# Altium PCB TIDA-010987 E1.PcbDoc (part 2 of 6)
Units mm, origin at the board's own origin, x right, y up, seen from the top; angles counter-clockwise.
Board outline 154.15 x 103.76 mm, 4 copper layers (5V, GND, MidSupply, -5V), stack 1.787 mm thick; 92 components, 52 nets, 1640 pads, 56 vias.
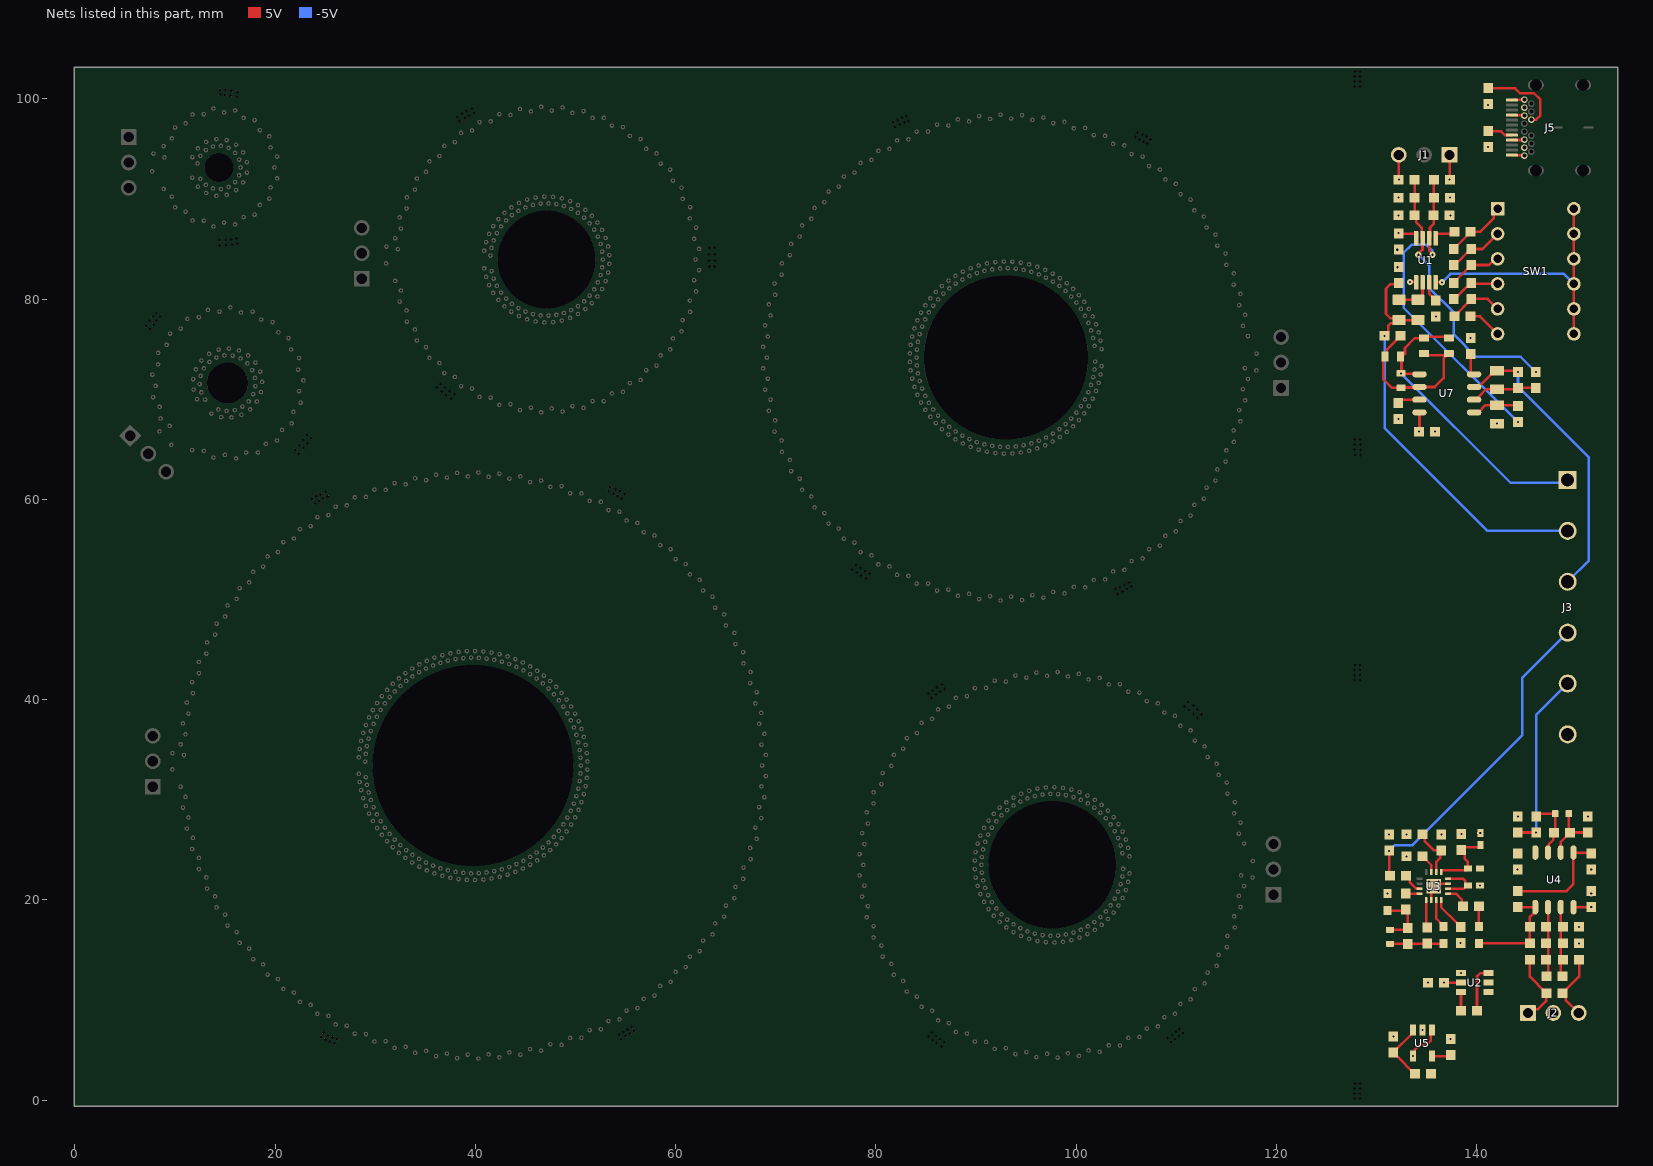
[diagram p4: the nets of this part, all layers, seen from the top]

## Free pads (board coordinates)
  round 0.254 hole 0.3 unplated mask+0: 0(7.105,77.291) 0(7.447,77.804) 0(7.521,77.001) 0(7.808,78.235) 0(7.843,77.464) 0(8.183,77.854) 0(8.189,78.604) 0(8.511,78.249) 0(14.482,100.405) 0(14.501,100.898) 0(15.028,100.383) 0(15.074,100.88) 0(15.577,100.316) 0(15.675,100.803) 0(16.132,100.178) 0(16.254,100.696) 0(21.983,64.939) 0(22.335,64.594) 0(22.448,65.44) 0(22.826,65.119) 0(22.847,65.936) 0(23.196,66.431) 0(23.24,65.629) 0(23.597,66.14) 0(23.717,60.012) 0(23.982,59.564) 0(24.16,60.277) 0(24.398,59.844) 0(24.566,60.496) 0(24.594,6.316) 0(24.805,60.077) 0(24.821,6.744) 0(25.026,6.067) 0(25.029,60.705) 0(25.257,60.291) 0(25.316,6.461) 0(25.498,5.843) 0(25.74,6.271) 0(25.945,5.627) 0(26.198,6.085) 0(53.282,60.84) 0(53.479,61.234) 0(53.801,60.602) 0(54.003,61.04) 0(54.207,60.344) 0(54.35,6.556) 0(54.455,60.817) 0(54.546,6.125) 0(54.659,60.091) 0(54.794,6.805) 0(54.91,60.532) 0(55.027,6.378) 0(55.21,7.056) 0(55.461,6.632) 0(55.618,7.275) 0(55.869,6.883)
  oval 0.2x0.254 hole 0.3 unplated mask+0: 0(14.462,85.357) 0(14.465,85.873) 0(15.041,85.873) 0(15.083,85.393) 0(15.615,85.945) 0(15.687,85.465) 0(16.134,86.05) 0(16.26,85.567)
  round 0.2 hole 0.3 unplated mask+0: 0(36.175,71.169) 0(36.513,71.523) 0(36.651,70.754) 0(36.961,71.144) 0(37.081,70.435) 0(37.402,70.823) 0(37.579,70.078) 0(37.917,70.524) 0(38.178,98.185) 0(38.439,97.801) 0(38.697,98.512) 0(38.951,98.073) 0(39.136,98.767) 0(39.363,98.317) 0(39.68,99.031) 0(39.889,98.582) 0(63.354,83.866) 0(63.361,84.44) 0(63.374,83.257) 0(63.397,85.094) 0(63.895,85.143) 0(63.908,83.238) 0(63.957,83.856) 0(63.957,84.427) 0(77.646,52.982) 0(78.018,53.44) 0(78.112,52.671) 0(78.467,53.122) 0(78.546,52.385) 0(78.906,52.841) 0(79.042,52.113) 0(79.348,52.602) 0(81.694,97.658) 0(81.927,97.201) 0(82.165,97.899) 0(82.392,97.415) 0(82.636,98.11) 0(82.852,97.613) 0(83.064,98.285) 0(83.277,97.759) 0(85.251,6.337) 0(85.253,40.596) 0(85.551,40.175) 0(85.634,6.749) 0(85.648,5.993) 0(85.678,40.922) 0(85.996,40.488) 0(86.008,6.417) 0(86.079,5.69) 0(86.136,41.23) 0(86.416,6.122) 0(86.429,40.788) 0(86.543,5.376) 0(86.592,41.51) 0(86.824,5.812) 0(86.85,41.057) 0(103.923,51.035) 0(104.142,50.566) 0(104.404,51.241) 0(104.646,50.802) 0(104.84,51.456) 0(105.085,51.032) 0(105.278,51.699) 0(105.535,51.299) 0(105.915,96.191) 0(106.159,96.628) 0(106.333,95.955) 0(106.621,96.435) 0(106.718,95.754) 0(107.033,96.212) 0(107.097,95.518) 0(107.455,95.949) 0(109.156,6.208) 0(109.458,5.803) 0(109.598,6.505) 0(109.904,6.116) 0(109.958,6.825) 0(110.291,6.395) 0(110.331,7.093) 0(110.703,6.677) 0(110.843,39.299) 0(111.193,39.762) 0(111.266,38.943) 0(111.704,38.562) 0(111.715,39.398) 0(112.113,38.136) 0(112.124,39.005) 0(112.536,38.511) 0(127.823,0.148) 0(127.823,0.648) 0(127.823,1.166) 0(127.823,41.952) 0(127.823,42.452) 0(127.823,42.969) 0(127.823,101.218) 0(127.823,101.718) 0(127.823,102.235) 0(127.827,64.953) 0(127.831,65.951) 0(127.834,64.447) 0(127.834,65.474) 0(127.845,1.636) 0(127.845,43.439) 0(127.845,102.705) 0(128.362,0.148) 0(128.362,0.647) 0(128.362,1.166) 0(128.362,1.636) 0(128.362,41.952) 0(128.362,42.451) 0(128.362,42.969) 0(128.362,43.439) 0(128.362,101.218) 0(128.362,101.716) 0(128.362,102.235) 0(128.362,102.705) 0(128.381,65.977) 0(128.387,65.452) 0(128.393,64.435) 0(128.393,64.934)
  round 0.45 hole 0.2 mask+0: 3(7.724,92.755) 3(9.646,65.446) 3(31.087,83.562) 3(117.66,23.878) 3(118.028,74.537) 4(7.858,94.525) 4(8.461,66.786) 4(31.133,85.225) 4(117.623,22.229) 4(117.999,72.885) 12(12.259,93.539) 12(13.022,69.953) 12(41.515,84.339) 12(101.914,73.758) 12(104.705,23.102) 13(8.962,94.156) 13(9.484,67.342) 13(32.273,84.985) 13(116.48,22.453) 13(116.853,73.096) 14(11.747,94.166) 14(12.211,69.994) 14(40.896,84.821) 14(102.552,73.305) 14(105.335,22.64) 15(8.573,68.071) 15(8.883,95.276) 15(32.001,86.071) 15(116.776,21.373) 15(117.166,72.008) 16(12.548,94.285) 16(12.634,70.686) 16(41.624,85.115) 16(101.844,72.971) 16(104.619,22.326) 17(8.484,69.234) 17(9.696,96.051) 17(32.562,87.041) 17(116.251,20.385) 17(116.666,70.992) 18(11.872,70.964) 18(12.297,95.055) 18(41.078,85.679) 18(102.44,72.463) 18(105.195,21.797) 19(7.828,70.199) 19(10.027,97.124) 19(32.443,88.155) 19(116.427,19.28) 19(116.882,69.88) 20(12.48,71.501) 20(13.087,94.876) 20(41.84,85.868) 20(101.705,72.194) 20(104.448,21.564) 21(8.086,71.337) 21(11.066,97.553) 21(33.134,89.036) 21(115.796,18.355) 21(116.294,68.912) 22(11.833,71.992) 22(13.131,95.684) 22(41.378,86.502) 22(102.254,71.635) 22(104.962,20.975) 23(7.744,72.453) 23(11.762,98.434) 23(33.172,90.156) 23(115.849,17.237) 23(116.411,67.786) 24(12.573,72.326) 24(13.803,95.232) 24(42.159,86.583) 24(101.498,71.432) 24(104.194,20.826) 25(8.326,73.464) 25(12.885,98.458) 25(33.979,90.933) 25(115.12,16.388) 25(115.74,66.874) 26(12.099,72.985) 26(14.136,95.97) 26(41.789,87.276) 26(101.995,70.827) 26(104.641,20.183) 27(8.327,74.631) 27(13.852,99.029) 27(34.172,92.036) 27(115.051,15.271) 27(115.757,65.741) 28(12.905,73.086) 28(14.599,95.306) 28(42.574,87.248) 28(101.224,70.691) 28(103.861,20.12) 29(9.182,75.426) 29(14.908,98.646) 29(35.079,92.693) 29(114.233,14.507) 29(115.008,64.892) 30(12.646,73.856) 30(15.176,95.874) 30(42.304,87.985) 30(101.666,70.045) 30(104.234,19.432) 31(9.527,76.54) 31(16.017,98.829) 31(35.423,93.759) 31(114.04,13.404) 31(114.924,63.763) 32(13.446,73.715) 32(15.368,95.087) 32(43.077,87.848) 32(100.886,69.977) 32(103.452,19.454) 33(10.578,77.048) 33(16.863,98.09) 33(36.413,94.284) 33(113.143,12.735) 33(114.103,62.983) 34(13.426,74.527) 34(16.111,95.408) 34(42.913,88.616) 34(101.269,69.295) 34(103.747,18.73) 35(11.236,78.011) 35(17.963,97.86) 35(36.903,95.291) 35(112.831,11.66) 35(113.92,61.865) 36(14.148,74.156) 36(16.006,94.606) 36(43.66,88.372) 36(100.486,69.296) 36(102.973,18.838) 37(12.39,78.186) 37(18.485,96.865) 37(37.956,95.673) 37(111.866,11.093) 37(113.033,61.161) 38(14.368,74.938) 38(16.815,94.636) 38(43.604,89.155) 38(100.807,68.583) 38(103.186,18.086) 39(13.303,78.913) 39(19.427,96.253) 39(38.581,96.602) 39(111.437,10.059) 39(112.753,60.064) 40(14.95,74.371) 40(16.427,93.926) 40(44.309,88.81) 40(100.028,68.653) 40(102.428,18.278) 41(14.457,78.74) 41(19.555,95.137) 41(39.677,96.833) 41(110.415,9.602) 41(111.807,59.441) 42(15.39,75.053) 42(17.193,93.662) 42(44.363,89.594) 42(100.284,67.914) 42(102.558,17.507) 43(15.544,79.165) 43(20.212,94.226) 43(40.425,97.667) 43(109.875,8.622) 43(111.43,58.373) 44(15.779,74.34) 44(16.574,93.14) 44(45.013,89.154) 44(99.514,68.053) 44(101.826,17.782) 45(16.596,78.66) 45(19.928,93.14) 45(41.543,97.743) 45(108.81,8.28) 45(110.433,57.836) 46(16.401,74.862) 46(17.193,92.617) 46(45.176,89.922) 46(99.704,67.294) 46(101.869,17.001) 47(17.76,78.746) 47(20.212,92.053) 47(42.4,98.465) 47(108.165,7.365) 47(109.963,56.806) 48(16.427,92.354) 48(16.562,74.066) 48(45.758,89.396) 48(98.95,67.501) 48(101.172,17.355) 49(18.616,77.953) 49(19.555,91.142) 49(43.517,98.385) 49(107.068,7.142) 49(108.923,56.359) 50(16.815,91.643) 50(17.31,74.381) 50(46.026,90.134) 50(99.072,66.728) 50(101.129,16.574) 51(19.427,90.026) 51(19.754,77.692) 51(44.466,98.98) 51(106.327,6.303) 51(108.364,55.374) 52(16.006,91.674) 52(17.229,73.573) 52(46.53,89.532) 52(98.339,67.001) 52(100.475,17.002) 53(18.485,89.414) 53(20.338,76.683) 53(45.562,98.745) 53(105.212,6.203) 53(107.288,55.021) 54(16.111,90.871) 54(18.037,73.654) 54(46.898,90.226) 54(98.392,66.22) 54(100.347,16.231) 55(17.963,88.419) 55(21.348,76.098) 55(46.584,99.203) 55(104.383,5.451) 55(106.644,54.089) 56(15.368,91.192) 56(17.722,72.906) 56(47.313,89.559) 56(97.686,66.557) 56(99.744,16.729) 57(16.863,88.189) 57(21.609,74.961) 57(47.636,98.818) 57(103.264,5.473) 57(105.541,53.833) 58(15.176,90.405) 58(18.518,72.745) 58(47.774,90.195) 58(97.67,65.774) 58(99.532,15.976) 59(16.017,87.45) 59(22.402,74.104) 59(48.713,99.128) 59(102.357,4.817) 59(104.818,52.962) 60(14.599,90.973) 60(17.996,72.123) 60(48.092,89.477) 60(96.996,66.172) 60(98.987,16.537) 61(14.908,87.633) 61(22.316,72.94) 61(49.701,98.601) 61(101.248,4.963) 61(103.696,52.804) 62(14.136,90.309) 62(18.709,71.735) 62(48.637,90.043) 62(96.911,65.394) 62(98.693,15.812) 63(13.852,87.25) 63(22.821,71.888) 63(50.81,98.759) 63(100.274,4.41) 63(102.898,52) 64(13.803,91.047) 64(18.027,71.294) 64(48.852,89.288) 64(96.275,65.85) 64(98.213,16.43) 65(12.885,87.821) 65(22.396,70.802) 65(51.715,98.099) 65(99.187,4.677) 65(101.767,51.942) 66(13.131,90.595) 66(18.594,70.713) 66(49.47,89.772) 66(96.122,65.082) 66(97.842,15.742) 67(11.762,87.845) 67(22.568,69.648) 67(52.835,98.1) 67(98.159,4.235) 67(100.902,51.211) 68(13.087,91.403) 68(17.812,70.493) 68(49.579,88.994) 68(95.528,65.593) 68(97.433,16.408) 69(11.066,88.727) 69(21.842,68.734) 69(53.64,97.321) 69(97.108,4.62) 69(99.77,51.253) 70(12.297,91.224) 70(18.182,69.77) 70(50.258,89.388) 70(95.308,64.842) 70(96.988,15.765) 71(10.027,89.155) 71(21.667,67.581) 71(54.749,97.167) 71(96.037,4.293) 71(98.843,50.602) 72(12.548,91.994) 72(17.371,69.79) 72(50.257,88.603) 72(94.762,65.402) 72(96.655,16.473) 73(9.697,90.228) 73(20.704,66.922) 73(55.438,96.283) 73(95.035,4.792) 73(97.72,50.744) 74(11.747,92.113) 74(17.512,68.991) 74(50.985,88.898) 74(94.476,64.674) 74(96.142,15.882) 75(8.883,91.003) 75(20.196,65.871) 75(56.515,95.976) 75(93.935,4.585) 75(96.739,50.178) 76(16.742,69.249) 76(50.875,88.12) 76(93.982,65.28) 76(95.888,16.622) 77(19.081,65.526) 77(57.074,95.005) 77(92.993,5.19) 77(95.633,50.418) 78(16.641,68.444) 78(51.636,88.311) 78(93.633,64.58) 78(95.314,16.092) 79(18.286,64.672) 79(58.098,94.551) 79(91.877,5.106) 79(94.606,49.941) 80(15.982,68.917) 80(51.419,87.557) 80(93.194,65.228) 80(95.143,16.855) 81(17.12,64.67) 81(58.516,93.512) 81(91.008,5.811) 81(93.525,50.278) 82(15.648,68.177) 82(52.2,87.64) 82(92.784,64.561) 82(94.513,16.392) 83(16.108,64.088) 83(59.467,92.92) 83(89.89,5.85) 83(92.46,49.893) 84(15.157,68.824) 84(51.879,86.923) 84(92.404,65.246) 84(94.428,17.169) 85(14.993,64.431) 85(59.736,91.832) 85(89.103,6.647) 85(91.413,50.325) 86(14.62,68.216) 86(52.664,86.896) 86(91.937,64.618) 86(93.751,16.777) 87(13.855,64.172) 87(60.595,91.113) 87(87.996,6.809) 87(90.318,50.036) 88(14.342,68.979) 88(52.247,86.231) 88(91.619,65.333) 88(93.752,17.559) 89(12.89,64.828) 89(60.711,89.999) 89(87.302,7.687) 89(89.313,50.558) 90(13.649,68.555) 90(53.021,86.096) 90(91.099,64.749) 90(93.036,17.245) 91(11.726,64.917) 91(61.461,89.168) 91(86.219,7.97) 91(88.197,50.367) 92(52.515,85.495) 92(90.845,65.489) 92(93.123,18.022) 93(61.421,88.048) 93(85.626,8.919) 93(87.242,50.976) 94(53.262,85.253) 94(90.275,64.953) 94(92.377,17.788) 95(62.048,87.121) 95(84.58,9.319) 95(86.113,50.884) 96(52.678,84.729) 96(90.088,65.713) 96(92.548,18.551) 97(61.852,86.018) 97(84.095,10.328) 97(85.216,51.575) 98(53.384,84.385) 98(89.473,65.23) 98(91.781,18.4) 99(62.345,85.012) 99(83.1,10.84) 99(84.084,51.584) 100(52.733,83.947) 100(89.354,66.003) 100(92.035,19.14) 101(61.997,83.947) 101(82.729,11.896) 101(83.251,52.351) 102(53.384,83.509) 102(88.698,65.576) 102(91.256,19.074) 103(62.345,82.882) 103(81.797,12.515) 103(82.124,52.46) 104(52.678,83.165) 104(88.648,66.357) 104(91.59,19.781) 105(61.852,81.876) 105(81.363,53.298) 105(81.544,13.606) 106(53.262,82.641) 106(87.957,65.989) 106(90.809,19.802) 107(62.048,80.773) 107(80.249,53.505) 107(80.685,14.324) 108(52.515,82.399) 108(87.976,66.772) 108(91.219,20.468) 109(61.421,79.846) 109(79.565,54.408) 109(80.554,15.435) 110(53.021,81.798) 110(87.255,66.467) 110(90.444,20.575) 111(61.461,78.726) 111(78.474,54.713) 111(79.779,16.243) 112(52.247,81.663) 112(87.343,67.244) 112(90.925,21.191) 113(60.711,77.895) 113(77.873,55.672) 113(79.771,17.362) 114(52.664,80.998) 114(86.598,67.004) 114(90.167,21.383) 115(60.595,76.781) 115(76.813,56.072) 115(79.09,18.251) 116(51.879,80.971) 116(86.754,67.771) 116(90.713,21.943) 117(59.736,76.062) 117(76.298,57.081) 117(79.205,19.364) 118(52.2,80.254) 118(85.991,67.598) 118(89.98,22.216) 119(59.467,74.974) 119(75.279,57.573) 119(78.626,20.322) 120(51.419,80.337) 120(86.215,68.348) 120(90.584,22.713) 121(58.516,74.382) 121(74.855,58.624) 121(78.863,21.416) 122(51.636,79.583) 122(85.44,68.242) 122(89.886,23.065) 123(58.098,73.343) 123(73.883,59.204) 123(78.392,22.431) 124(50.875,79.774) 124(85.728,68.97) 124(90.541,23.493) 125(57.074,72.889) 125(73.554,60.288) 125(78.748,23.493) 126(50.985,78.996) 126(84.947,68.933) 126(89.886,23.92) 127(56.515,71.918) 127(72.636,60.952) 127(78.392,24.554) 128(50.257,79.291) 128(85.299,69.632) 128(90.584,24.272) 129(55.438,71.611) 129(72.404,62.06) 129(78.863,25.57) 130(50.258,78.506) 130(84.517,69.665) 130(89.98,24.769) 131(54.749,70.727) 131(71.549,62.803) 131(78.626,26.664) 132(49.579,78.9) 132(84.929,70.33) 132(90.713,25.042) 133(53.64,70.573) 133(71.416,63.928) 133(79.205,27.621) 134(49.47,78.122) 134(84.154,70.432) 134(90.167,25.603) 135(52.835,69.794) 135(70.63,64.743) 135(79.09,28.735) 136(48.852,78.606) 136(84.623,71.058) 136(90.925,25.794) 137(51.715,69.795) 137(70.597,65.875) 137(79.771,29.623) 138(48.637,77.851) 138(83.859,71.228) 138(90.444,26.411) 139(50.81,69.135) 139(69.886,66.756) 139(79.779,30.742) 140(48.092,78.417) 140(84.382,71.81) 140(91.219,26.517) 141(49.701,69.293) 141(69.953,67.887) 141(80.554,31.55) 142(47.774,77.699) 142(83.637,72.047) 142(90.809,27.183) 143(48.713,68.766) 143(69.323,68.828) 143(80.685,32.662) 144(47.313,78.335) 144(84.209,72.581) 144(91.59,27.204) 145(47.636,69.076) 145(69.489,69.948) 145(81.544,33.38) 146(46.898,77.668) 146(83.487,72.883) 146(91.256,27.911) 147(46.584,68.691) 147(68.945,70.941) 147(81.797,34.47) 148(46.53,78.362) 148(84.105,73.364) 148(92.035,27.846) 149(45.562,69.149) 149(69.21,72.042) 149(82.729,35.089) 150(46.026,77.76) 150(83.412,73.728) 150(91.781,28.585) 151(44.466,68.914) 151(68.755,73.079) 151(83.1,36.145) 152(45.758,78.498) 152(84.07,74.152) 152(92.548,28.435) 153(43.517,69.509) 153(69.116,74.152) 153(84.095,36.658) 154(45.176,77.972) 154(83.412,74.577) 154(92.377,29.197) 155(42.4,69.429) 155(68.755,75.226) 155(84.58,37.666) 156(45.013,78.74) 156(84.105,74.941) 156(93.123,28.963) 157(41.543,70.151) 157(69.21,76.263) 157(85.626,38.066) 158(44.363,78.3) 158(83.487,75.422) 158(93.036,29.741) 159(40.425,70.227) 159(68.945,77.364) 159(86.219,39.016) 160(44.309,79.084) 160(84.209,75.724) 160(93.752,29.426) 161(39.677,71.061) 161(69.489,78.357) 161(87.302,39.298) 162(43.604,78.739) 162(83.637,76.258) 162(93.751,30.208) 163(38.581,71.292) 163(69.323,79.477) 163(87.996,40.177) 164(43.66,79.522) 164(84.382,76.495) 164(94.428,29.816) 165(37.956,72.221) 165(69.953,80.418) 165(89.103,40.338) 166(42.913,79.278) 166(83.859,77.077) 166(94.513,30.594) 167(36.903,72.603) 167(69.886,81.549) 167(89.89,41.135) 168(43.077,80.046) 168(84.623,77.247) 168(95.143,30.13) 169(36.413,73.61) 169(70.597,82.43) 169(91.008,41.174) 170(42.304,79.909) 170(84.154,77.873) 170(95.314,30.893) 171(35.423,74.135) 171(70.63,83.562) 171(91.877,41.879) 172(42.574,80.646) 172(84.929,77.975) 172(95.888,30.363) 173(35.079,75.201) 173(71.416,84.377) 173(92.993,41.795) 174(41.789,80.618) 174(84.517,78.64) 174(96.142,31.103) 175(34.172,75.858) 175(71.549,85.502) 175(93.935,42.4) 176(42.159,81.311) 176(85.299,78.673) 176(96.655,30.513) 177(33.979,76.961) 177(72.404,86.245) 177(95.035,42.194) 178(41.378,81.392) 178(84.947,79.372) 178(96.988,31.22) 179(33.172,77.738) 179(72.636,87.353) 179(96.037,42.692) 180(41.84,82.026) 180(85.728,79.335) 180(97.433,30.577) 181(33.134,78.858) 181(73.554,88.017) 181(97.108,42.365) 182(41.078,82.215) 182(85.44,80.063) 182(97.842,31.244) 183(32.443,79.739) 183(73.883,89.101) 183(98.159,42.75) 184(41.624,82.779) 184(86.215,79.957) 184(98.213,30.556) 185(32.562,80.853) 185(74.855,89.681) 185(99.187,42.308) 186(40.896,83.073) 186(85.991,80.707) 186(98.693,31.173) 187(32.001,81.823) 187(75.279,90.732) 187(100.274,42.575) 188(86.754,80.534) 188(98.987,30.448) 189(76.298,91.224) 189(101.248,42.022) 190(86.598,81.301) 190(99.532,31.009) 191(76.813,92.233) 191(102.357,42.168) 192(87.343,81.061) 192(99.744,30.257) 193(77.873,92.633) 193(103.264,41.512) 194(87.255,81.838) 194(100.347,30.754) 195(78.474,93.592) 195(104.383,41.535) 196(87.976,81.533) 196(100.475,29.983) 197(79.565,93.897) 197(105.212,40.782) 198(87.957,82.316) 198(101.129,30.411) 199(80.249,94.8) 199(106.327,40.682) 200(88.648,81.948) 200(101.172,29.63) 201(81.363,95.007) 201(107.068,39.843) 202(88.698,82.729) 202(101.869,29.984) 203(82.124,95.845) 203(108.165,39.621) 204(89.354,82.302) 204(101.826,29.203) 205(83.251,95.954) 205(108.81,38.705) 206(89.473,83.075) 206(102.558,29.478) 207(84.084,96.721) 207(109.875,38.364) 208(90.088,82.592) 208(102.428,28.707) 209(85.216,96.73) 209(110.415,37.383) 210(90.275,83.352) 210(103.186,28.9) 211(86.113,97.421) 211(111.437,36.926) 212(90.845,82.816) 212(102.973,28.147) 213(87.242,97.329) 213(111.866,35.892) 214(91.099,83.556) 214(103.747,28.255) 215(88.197,97.938) 215(112.831,35.325) 216(91.619,82.972) 216(103.452,27.531) 217(89.313,97.747) 217(113.143,34.251) 218(91.937,83.687) 218(104.234,27.553) 219(90.318,98.269) 219(114.04,33.581) 220(92.404,83.059) 220(103.861,26.866) 221(91.413,97.98) 221(114.233,32.479) 222(92.784,83.744) 222(104.641,26.802) 223(92.46,98.412) 223(115.051,31.714) 224(93.194,83.077) 224(104.194,26.16) 225(93.525,98.027) 225(115.12,30.597) 226(93.633,83.725) 226(104.962,26.01) 227(94.606,98.364) 227(115.849,29.748) 228(93.982,83.025) 228(104.448,25.421) 229(95.633,97.887) 229(115.796,28.63) 230(94.476,83.631) 230(105.195,25.188) 231(96.739,98.127) 231(116.427,27.706) 232(94.762,82.903) 232(104.619,24.659) 233(97.72,97.561) 233(116.251,26.6) 234(95.308,83.463) 234(105.335,24.346) 235(98.843,97.702) 235(116.776,25.612) 236(95.528,82.712) 237(99.77,97.052) 238(96.122,83.222) 239(100.902,97.094) 240(96.275,82.455) 241(101.767,96.363) 242(96.911,82.911) 243(102.898,96.305) 244(96.996,82.133) 245(103.696,95.501) 246(97.67,82.53) 247(104.818,95.343) 248(97.686,81.748) 249(105.541,94.472) 250(98.392,82.085) 251(106.644,94.216) 252(98.339,81.304) 253(107.288,93.284) 254(99.072,81.577) 255(108.364,92.931) 256(98.95,80.804) 257(108.923,91.946) 258(99.704,81.011) 259(109.963,91.499) 260(99.514,80.252) 261(110.433,90.469) 262(100.284,80.391) 263(111.43,89.932) 264(100.028,79.652) 265(111.807,88.864) 266(100.807,79.722) 267(112.753,88.241) 268(100.486,79.009) 269(113.033,87.144) 270(101.269,79.01) 271(113.92,86.44) 272(100.886,78.328) 273(114.103,85.322) 274(101.666,78.26) 275(114.924,84.542) 276(101.224,77.614) 277(115.008,83.413) 278(101.995,77.478) 279(115.757,82.564) 280(101.498,76.873) 281(115.74,81.431) 282(102.254,76.67) 283(116.411,80.519) 284(101.705,76.111) 285(116.294,79.393) 286(102.44,75.842) 287(116.882,78.425) 288(101.844,75.334) 289(116.666,77.313) 290(102.552,75) 291(117.166,76.297)
  round 0.45 hole 0.2 mask-2539.97: 3(9.738,33.027) 4(9.761,34.657) 12(29.012,33.801) 13(10.909,34.455) 14(28.368,34.237) 15(10.582,35.524) 16(29.068,34.576) 17(11.06,36.535) 18(28.457,35.058) 19(10.81,37.625) 20(29.18,35.346) 21(11.36,38.598) 22(28.605,35.87) 23(11.19,39.703) 24(29.347,36.105) 25(11.808,40.635) 26(28.812,36.669) 27(11.718,41.749) 28(29.568,36.85) 29(12.402,42.634) 30(29.075,37.452) 31(12.393,43.752) 32(29.843,37.577) 33(13.139,44.585) 34(29.395,38.213) 35(13.21,45.7) 36(30.169,38.283) 37(14.015,46.477) 38(29.768,38.949) 39(14.166,47.585) 40(30.546,38.963) 41(15.025,48.302) 42(30.194,39.656) 43(15.256,49.395) 44(30.97,39.614) 45(16.164,50.048) 46(30.669,40.331) 47(16.473,51.123) 48(31.441,40.233) 49(17.425,51.708) 50(31.192,40.97) 51(17.812,52.758) 52(31.955,40.816) 53(18.804,53.273) 54(31.76,41.569) 55(19.265,54.292) 56(32.509,41.361) 57(20.292,54.734) 58(32.369,42.126) 59(20.825,55.717) 60(33.102,41.864) 61(21.881,56.084) 62(33.017,42.637) 63(22.484,57.026) 64(33.729,42.323) 65(23.564,57.316) 66(33.701,43.101) 67(24.233,58.212) 68(34.388,42.736) 69(25.331,58.423) 70(34.415,43.513) 71(26.063,59.268) 72(35.074,43.1) 73(27.173,59.4) 74(35.158,43.873) 75(27.964,60.19) 76(35.786,43.414) 77(29.081,60.241) 78(35.925,44.179) 79(29.927,60.972) 80(36.518,43.675) 81(31.045,60.943) 82(36.712,44.428) 83(31.941,61.611) 84(37.267,43.883) 85(33.054,61.5) 86(37.515,44.62) 87(33.997,62.102) 88(38.029,44.036) 89(35.098,61.912) 90(38.33,44.754) 91(36.082,62.444) 92(38.8,44.134) 93(37.167,62.175) 94(39.152,44.828) 95(38.186,62.634) 96(39.576,44.177) 97(39.249,62.288) 98(39.977,44.843) 99(40.299,62.673) 100(40.354,44.163) 101(41.334,62.25) 102(40.801,44.799) 103(42.409,62.558) 104(41.128,44.092) 105(43.411,62.062) 106(41.62,44.695) 107(44.505,62.292) 108(41.895,43.967) 109(45.469,61.725) 110(42.43,44.532) 111(46.577,61.875) 112(42.651,43.786) 113(47.497,61.24) 114(43.225,44.311) 115(48.613,61.31) 116(43.392,43.551) 117(49.485,60.61) 118(44.002,44.033) 119(50.603,60.599) 120(44.114,43.263) 121(51.422,59.838) 122(44.758,43.7) 123(52.536,59.746) 124(44.814,42.924) 125(53.298,58.928) 126(45.487,43.313) 127(54.403,58.757) 128(45.487,42.536) 129(55.104,57.886) 130(46.187,42.875) 131(56.194,57.635) 132(46.13,42.099) 133(56.83,56.715) 134(46.853,42.388) 135(57.899,56.386) 136(46.74,41.618) 137(58.467,55.424) 138(47.482,41.853) 139(59.509,55.018) 140(47.314,41.093) 141(60.007,54.017) 142(48.071,41.275) 143(61.017,53.538) 144(47.849,40.529) 145(61.441,52.503) 146(48.617,40.655) 147(62.414,51.952) 148(48.341,39.928) 149(62.762,50.89) 150(49.116,39.998) 151(63.693,50.27) 152(48.789,39.292) 153(63.963,49.185) 154(49.567,39.307) 155(64.847,48.5) 156(49.19,38.626) 157(65.038,47.398) 158(49.967,38.584) 159(65.87,46.651) 160(49.542,37.933) 161(65.981,45.539) 162(50.313,37.835) 163(66.757,44.733) 164(49.842,37.216) 165(66.788,43.616) 166(50.605,37.063) 167(67.504,42.757) 168(50.091,36.479) 169(67.454,41.64) 170(50.84,36.272) 171(68.106,40.731) 172(50.285,35.727) 173(67.975,39.621) 174(51.018,35.465) 175(68.56,38.668) 176(50.425,34.962) 177(68.35,37.569) 178(51.136,34.648) 179(68.864,36.576) 180(50.509,34.189) 181(68.575,35.496) 182(51.196,33.825) 183(69.017,34.469) 184(50.537,33.412) 185(68.651,33.412) 186(51.196,33) 187(69.017,32.356) 188(50.509,32.635) 189(68.575,31.328) 190(51.136,32.176) 191(68.864,30.248) 192(50.425,31.863) 193(68.35,29.255) 194(51.018,31.359) 195(68.56,28.157) 196(50.285,31.098) 197(67.975,27.204) 198(50.84,30.553) 199(68.106,26.093) 200(50.091,30.345) 201(67.454,25.185) 202(50.605,29.762) 203(67.504,24.068) 204(49.842,29.609) 205(66.788,23.209) 206(50.313,28.99) 207(66.757,22.091) 208(49.542,28.892) 209(65.981,21.286) 210(49.967,28.24) 211(65.87,20.173) 212(49.19,28.199) 213(65.038,19.426) 214(49.567,27.518) 215(64.847,18.325) 216(48.789,27.532) 217(63.963,17.639) 218(49.116,26.827) 219(63.693,16.555) 220(48.341,26.897) 221(62.762,15.935) 222(48.617,26.169) 223(62.414,14.872) 224(47.849,26.296) 225(61.441,14.321) 226(48.071,25.55) 227(61.017,13.287) 228(47.314,25.731) 229(60.007,12.808) 230(47.482,24.972) 231(59.509,11.806) 232(46.74,25.207) 233(58.467,11.401) 234(46.853,24.437) 235(57.899,10.438) 236(46.13,24.725) 237(56.83,10.109) 238(46.187,23.95) 239(56.194,9.19) 240(45.487,24.289) 241(55.104,8.939) 242(45.487,23.511) 243(54.403,8.068) 244(44.814,23.9) 245(53.298,7.897) 246(44.758,23.125) 247(52.536,7.078) 248(44.114,23.561) 249(51.422,6.987) 250(44.002,22.791) 251(50.603,6.226) 252(43.392,23.274) 253(49.485,6.215) 254(43.225,22.514) 255(48.613,5.515) 256(42.651,23.039) 257(47.497,5.585) 258(42.43,22.293) 259(46.577,4.95) 260(41.895,22.858) 261(45.469,5.1) 262(41.62,22.13) 263(44.505,4.533) 264(41.128,22.732) 265(43.411,4.763) 266(40.801,22.026) 267(42.409,4.266) 268(40.354,22.662) 269(41.334,4.575) 270(39.977,21.981) 271(40.299,4.152) 272(39.576,22.648) 273(39.249,4.537) 274(39.152,21.996) 275(38.186,4.19) 276(38.8,22.69) 277(37.167,4.65) 278(38.33,22.071) 279(36.082,4.381) 280(38.029,22.788) 281(35.098,4.913) 282(37.515,22.204) 283(33.997,4.723) 284(37.267,22.942) 285(33.054,5.324) 286(36.712,22.396) 287(31.941,5.214) 288(36.518,23.15) 289(31.045,5.882) 290(35.925,22.646) 291(29.927,5.852) 292(35.786,23.411) 293(29.081,6.583) 294(35.158,22.951) 295(27.964,6.635) 296(35.074,23.725) 297(27.173,7.425) 298(34.415,23.311) 299(26.063,7.556) 300(34.388,24.089) 301(25.331,8.402) 302(33.701,23.724) 303(24.233,8.613) 304(33.729,24.501) 305(23.564,9.509) 306(33.017,24.187) 307(22.484,9.799) 308(33.102,24.961) 309(21.881,10.74) 310(32.369,24.699) 311(20.825,11.108) 312(32.509,25.464) 313(20.292,12.09) 314(31.76,25.255) 315(19.265,12.533) 316(31.955,26.009) 317(18.804,13.552) 318(31.192,25.855) 319(17.812,14.067) 320(31.441,26.592) 321(17.425,15.116) 322(30.669,26.493) 323(16.473,15.702) 324(30.97,27.211) 325(16.164,16.776) 326(30.194,27.168) 327(15.256,17.429) 328(30.546,27.862) 329(15.025,18.523) 330(29.768,27.876) 331(14.166,19.24) 332(30.169,28.542) 333(14.015,20.348) 334(29.395,28.612) 335(13.21,21.124) 336(29.843,29.248) 337(13.139,22.24) 338(29.075,29.373) 339(12.393,23.073) 340(29.568,29.975) 341(12.402,24.191) 342(28.812,30.155) 343(11.718,25.075) 344(29.347,30.72) 345(11.808,26.19) 346(28.605,30.955) 347(11.19,27.121) 348(29.18,31.479) 349(11.36,28.226) 350(28.457,31.767) 351(10.81,29.2) 352(29.068,32.248) 353(11.06,30.29) 354(28.368,32.587) 355(10.582,31.301)
  round 2.882 hole 2.882 unplated mask+0: Un1(14.398,93.14)
  round 4.096 hole 4.096 unplated mask+0: Un1(15.261,71.606)
  round 20.062 hole 20.062 unplated mask+0: Un1(39.771,33.412)
  round 9.761 hole 9.761 unplated mask+0: Un1(47.117,83.947)
  round 16.383 hole 16.383 unplated mask+0: Un1(92.996,74.152)
  round 12.704 hole 12.704 unplated mask+0: Un1(97.628,23.493)

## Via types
v1: diameter 0.61, hole 0.203, 5V to -5V, tented both sides, 52 vias
v2: diameter 0.5, hole 0.2, 5V to -5V, tented both sides, 4 vias

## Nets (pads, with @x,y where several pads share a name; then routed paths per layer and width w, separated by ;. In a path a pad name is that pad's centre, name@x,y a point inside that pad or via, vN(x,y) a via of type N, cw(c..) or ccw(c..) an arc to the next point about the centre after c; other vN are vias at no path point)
1_RG_P1: R40.1 U1.1 | length 2.4
  5V w0.254: U1.1@135.899,86.064 135.899,86.416 135.997,86.514 137.588,86.514 R40.1@137.79,86.716
2_RG_P1: SW1.7 SW1.8 SW1.9 SW1.10 SW1.11 SW1.12 U1.8 | length 27.1
  5V w0.254: U1.8@135.899,81.664 135.908,81.672 v1(136.534,81.672) ; SW1.7@149.72,76.514 SW1.8@149.72,79.014 SW1.9@149.72,81.514 SW1.10@149.72,84.014 SW1.11@149.72,86.514 SW1.12@149.72,89.014
  -5V w0.254: v1(136.534,81.672) 137.377,82.516 148.718,82.516 SW1.9@149.72,81.514
5V: C7.2 C8.2 C19.2 C31.1 J5.A4 J5.A9 J5.B4 J5.B9 R9.2 R22.2 U1.7 U2.4 U2.5 U4.8 U5.5 U7.8 | length 8.8
  5V w0.254: U1.7@135.249,81.664 135.249,80.546 135.924,79.871 C7.2@135.924,79.846 ; U5.5@135.546,4.395 137.277,4.395 C31.1@137.402,4.52 ; C8.2@139.405,74.53 139.405,72.644 139.564,72.484 U7.8@139.748,72.484 ; J5.A4@143.518,95.86 143.541,95.883 144.741,95.883 J5.B9@144.768,95.91 ; J5.A9@143.518,98.36 143.541,98.337 144.741,98.337 J5.B4@144.768,98.31
-5V: C10.2 C11.1 C25.2 C32.2 U1.4 U2.2 U4.4 U7.4 | length 7.5
  5V w0.254: C11.1@132.211,86.527 133.851,86.527 133.949,86.429 U1.4@133.949,86.064 ; v1(134.227,66.769) 134.298,66.839 U7.4@134.298,68.674 ; v1(136.767,11.731) U2.2@138.44,11.731 ; U4.4@149.674,19.271 151.444,19.271 v1(151.452,19.279)
  other v1: 132.211,86.602
amp_out: C6.1 C9.2 J3.2 R4.1 R7.1 | length 41.8
  5V w0.254: R4.1@130.843,76.33 131.191,76.678 131.191,77.343 131.424,77.576 131.925,77.576 C6.1@132.246,77.897 132.056,78.088 131.379,78.088 130.954,78.513 130.954,81.048 131.365,81.458 132.094,81.458 R7.1@132.22,81.584 ; C6.1@132.119,77.897 C9.2@134.152,77.897
  -5V w0.254: v1(130.823,76.33) 130.823,67.118 141.096,56.845 J3.2@149.098,56.845
GND: C1.2 C2.1 C7.1 C8.1 C10.1 C11.2 C14.1 C15.2 C16.1 C18.2 C19.1 C20.1 C22.1 C24.2 C25.1 C31.2 C32.1 C36.1 J3.6 J5.1 J5.2 J5.A1 J5.A12 J5.B1 J5.B12 R3.1 R5.2 R7.2 R8.1 R14.2 R17.1 R21.2 R25.2 R26.1 R27.1 U1.5 U2.1 U3.10 U3.15 U3.17 U5.2 | length 5.5
  5V w0.254: v1@133.212,81.723 133.89,81.723 U1.5@133.949,81.664 ; v2(135.247,20.898) 135.349,20.898 135.472,20.775 U3.10@135.472,19.973 ; v2(136.197,21.848) 136.197,21.746 136.32,21.623 U3.15@137.122,21.623 ; J5.A1@143.518,94.36 143.541,94.337 144.741,94.337 J5.B12@144.768,94.31 ; J5.A12@143.518,99.86 143.541,99.883 144.741,99.883 J5.B1@144.768,99.91
  other v1: 137.402,6.12 131.699,6.361 134.596,6.995 135.167,11.731 138.44,12.681 138.415,15.696 131.116,20.628 151.452,20.629 140.331,21.423 144.086,23.018 132.981,24.34 131.255,26.537 132.981,26.537 136.472,26.537 138.481,26.562 140.366,26.662 144.123,28.324 135.827,66.769 142.047,67.559 132.191,68.031 139.405,76.13 135.924,78.246 133.368,81.703 132.088,83.174 132.075,84.923 132.22,88.359 137.39,88.359 132.22,90.137 137.323,90.137 141.141,95.161 141.152,99.395
  other v2: 136.197,20.898 135.247,21.848
INPUT_1_N: J1.1 R2.2 | length 2.5
  5V w0.254: v1(137.315,91.934) J1.1@137.315,94.397
INPUT_1_P: J1.3 R6.2 | length 2.5
  5V w0.254: v1(132.235,91.93) J1.3@132.235,94.397
INPUT_2_N: J2.1 R16.1 R23.1 | length 7.1
  5V w0.254: J2.1@145.126,8.701 145.512,9.087 146.143,9.087 146.944,9.888 R16.1@146.944,10.693 ; R23.1@145.316,14.028 145.316,12.321 R16.1@146.944,10.693 ; R16.1@146.969,10.693 R16.1@146.944,10.693
INPUT_2_P: J2.3 R13.1 R16.2 | length 6.7
  5V w0.254: J2.3@150.206,8.701 148.894,10.013 148.894,10.368 R16.2@148.569,10.693 148.594,10.693 150.244,12.343 R13.1@150.244,14.028
INT-input-N: C1.1 R2.1 R3.2 R43.1 U1.2 | length 33.3
  5V w0.254: v1(135.589,84.422) 135.589,84.518 135.249,84.857 U1.2@135.249,86.064 135.347,86.162 135.347,87.136 135.715,87.503 R3.2@135.715,88.359 135.734,88.378 R2.1@135.734,91.915
  -5V w0.254: v1(135.589,84.422) 135.56,84.45 135.56,84.855 135.001,85.414 133.501,85.414 132.724,84.636 132.724,79.117 v1(144.135,67.706)
INT-input-P: C2.2 R5.1 R6.1 R42.1 U1.3 | length 27.2
  5V w0.254: R6.1@133.82,91.915 R5.1@133.82,90.137 C2.2@133.82,88.359 133.978,88.201 133.978,87.652 134.501,87.129 134.501,86.162 U1.3@134.599,86.064 134.599,84.941 134.176,84.518 v1(134.176,84.422)
  -5V w0.254: v1(134.176,84.422) 135.249,83.348 135.249,81.123 137.73,78.643 137.73,76.438 139.945,74.223 144.407,74.223 v1(145.91,72.72)
int_amp_out: C3.2 C4.2 C5.2 J3.1 R1.1 U7.1 | length 30.6
  5V w0.254: U7.1@134.298,72.484 134.255,72.527 132.57,72.527 132.498,72.598 132.498,74.197 132.548,74.247 132.85,74.548 132.85,75.121 133.826,76.097 134.6,76.097 134.758,76.255 C5.2@137.221,76.255
  -5V w0.254: v1(132.47,72.57) 143.39,61.651 148.824,61.651 J3.1@149.098,61.925
int_out: C37.2 J3.3 R41.2 U7.7 | length 29.9
  5V w0.254: U7.7@139.748,71.214 140.191,71.214 141.822,72.845 C37.2@142.047,72.845 144.01,72.845 v1(144.135,72.72)
  -5V w0.254: v1(144.135,72.72) 144.135,71.255 151.216,64.174 151.216,53.883 J3.3@149.098,51.765
intOut: C23.2 C28.1 R20.1 R28.2 U4.1 | length 10.7
  5V w0.254: R20.1@140.231,15.646 C28.1@145.316,15.646 R28.2@145.316,17.297 145.316,18.298 145.864,18.846 U4.1@145.864,19.271 144.093,19.271 C23.2@144.086,19.279
LNA_O: R24.1 U3.11 | length 2.9
  5V w0.254: U3.11@135.972,19.973 135.972,18.115 136.691,17.396 R24.1@136.691,17.346
Log_out: C18.1 J3.4 R11.2 | length 32.8
  5V w0.254: C18.1@131.255,24.937 131.255,22.464 R11.2@131.33,22.389
  -5V w0.254: v1(131.255,24.862) 131.859,25.466 133.6,25.466 144.551,36.417 144.551,42.138 J3.4@149.098,46.685
Main_out: C24.1 J3.5 R19.2 | length 18
  5V w0.254: C24.1@144.123,26.724 v1(145.941,26.724)
  -5V w0.254: v1(145.941,26.724) 145.941,38.448 J3.5@149.098,41.605
MidSupply: C13.1 J2.2 R12.2 R15.1 R18.2 U5.1 U5.4 | length 3.6
  5V w0.254: v1(133.646,4.395) 133.819,4.568 133.819,5.018 134.321,5.521 135.021,5.521 135.423,5.923 U5.1@135.423,6.873
  other v1: 150.244,15.646 150.244,17.297 151.452,23.017 151.109,28.324
NetC3_1: C3.1 C4.1 C5.1 R1.2 R4.2 U7.2 | length 16.9
  5V w0.254: R4.2@132.423,76.33 132.398,76.33 131.046,74.978 131.046,74.595 130.698,74.247 130.698,71.987 131.565,71.12 R1.2@132.47,71.12 132.517,71.167 134.251,71.167 U7.2@134.298,71.214 135.814,71.214 136.7,72.1 136.7,74.057 C5.1@137.048,74.405 ; C3.1@134.758,74.405 C5.1@137.048,74.405 ; C5.1@137.221,74.405 C5.1@137.048,74.405 ; C5.1@137.221,74.405 C5.1@137.048,74.405
NetC6_2: C6.2 C9.1 U1.6 | length 3.8
  5V w0.254: C6.2@132.246,79.929 C9.1@134.152,79.929 ; C9.1@134.218,79.929 134.599,80.31 U1.6@134.599,81.664
NetC12_1: C12.1 U3.13 | length 2.4
  5V w0.254: U3.13@137.122,20.623 137.931,20.623 138.499,20.055 138.499,19.479 C12.1@138.631,19.348
NetC12_2: C12.2 R20.2 | length 2
  5V w0.254: R20.2@140.231,17.346 C12.2@140.231,19.348
NetC13_2: C13.2 C21.1 R12.1 R13.2 U4.3 | length 7
  5V w0.254: U4.3@148.404,19.271 148.404,12.509 C21.1@148.569,12.344
NetC14_2: C14.2 C16.2 R9.1 U3.1 | length 7.1
  5V w0.254: U3.1@136.472,22.773 136.472,22.939 136.485,22.952 138.968,22.952 R9.1@139.131,23.114 139.131,23.795 138.829,24.097 138.829,24.614 C14.2@138.481,24.962 138.749,25.231 140.193,25.231 140.366,25.404 C16.2@140.366,25.462
NetC15_1: C15.1 U3.14 U3.16 | length 4.6
  5V w0.254: U3.14@137.122,21.123 138.731,21.123 139.031,21.423 C15.1@139.131,21.423 139.046,21.423 138.873,21.596 138.873,21.896 138.646,22.123 U3.16@137.122,22.123
NetC17_1: C17.1 R10.1 R15.2 U4.6 | length 6.1
  5V w0.254: U4.6@148.404,24.721 148.404,25.793 149.306,26.695 R10.1@149.331,26.695 ; C17.1@149.206,28.6 149.206,26.82 R10.1@149.331,26.695 ; R15.2@151.109,26.724 149.359,26.724 R10.1@149.331,26.695
NetC17_2: C17.2 R10.2 R19.1 U4.7 | length 6.2
  5V w0.254: R19.1@145.941,28.324 146.217,28.6 C17.2@147.856,28.6 147.856,26.82 R10.2@147.731,26.695 147.655,26.62 147.655,25.988 147.2,25.533 147.2,24.788 U4.7@147.134,24.721
NetC20_2: C20.2 R17.2 U3.2 | length 5.2
  5V w0.254: C20.2@134.581,26.537 134.845,26.273 134.845,25.83 135.737,24.937 R17.2@136.472,24.937 ; U3.2@135.972,22.773 135.972,23.795 136.383,24.205 136.383,24.872 R17.2@136.472,24.962
NetC21_2: C21.2 C28.2 R23.2 R28.1 U4.2 | length 7
  5V w0.254: C21.2@146.969,12.344 147.134,12.509 U4.2@147.134,19.271
NetC22_2: C22.2 U3.12 | length 3.5
  5V w0.254: U3.12@136.472,19.973 136.472,19.239 138.042,17.669 138.067,17.669 138.415,17.321 C22.2@138.415,17.296
NetC23_1: C23.1 R18.1 U4.5 | length 10.9
  5V w0.254: C23.1@144.086,20.879 148.99,20.879 149.674,21.563 U4.5@149.674,24.721 151.348,24.721 R18.1@151.452,24.617
NetC26_1: C26.1 C27.1 L1.2 R24.2 | length 5.4
  5V w0.254: L1.2@131.355,15.611 136.655,15.611 R24.2@136.691,15.646
NetC26_2: C26.2 U3.9 | length 2.8
  5V w0.254: U3.9@134.972,19.973 134.972,17.318 C26.2@135.052,17.238
NetC27_2: C27.2 C29.1 L1.1 R27.2 | length 5.6
  5V w0.254: R27.2@131.116,18.928 132.835,18.928 C29.1@132.93,19.023 133.105,18.848 C27.2@133.105,17.209 132.906,17.011 L1.1@131.355,17.011
NetC29_2: C29.2 U3.8 | length 1.4
  5V w0.254: C29.2@132.93,20.623 U3.8@134.322,20.623
NetC30_1: C30.1 U2.3 | length 1.8
  5V w0.254: C30.1@138.439,8.937 138.44,8.939 U2.3@138.44,10.781
NetC30_2: C30.2 U2.6 | length 4.7
  5V w0.254: C30.2@140.039,8.937 140.039,12.353 140.367,12.681 U2.6@141.19,12.681
NetC36_2: C36.2 R43.2 U7.5 | length 4.7
  5V w0.254: U7.5@139.748,68.674 140.173,68.674 140.908,69.409 C36.2@142.047,69.409 144.032,69.409 R43.2@144.135,69.306
NetC37_1: C37.1 R41.1 R42.2 U7.6 | length 6.7
  5V w0.254: U7.6@139.748,69.944 140.079,69.944 140.239,70.104 140.239,70.268 140.966,70.995 C37.1@142.047,70.995 144.01,70.995 R41.1@144.135,71.12 R42.2@145.91,71.12
NetJ5_A5: J5.A5 R14.1 | length 2.5
  5V w0.254: R14.1@141.141,96.736 142.459,96.736 142.811,96.383 142.953,96.383 143.495,96.383 J5.A5@143.518,96.36
NetJ5_B5: J5.B5 R21.1 | length 8.3
  5V w0.254: R21.1@141.152,101.07 141.185,101.038 143.835,101.038 144.31,100.562 145.266,100.562 145.275,100.553 145.72,100.553 146.363,99.91 146.363,98.347 145.942,97.926 145.484,97.926 J5.B5@145.468,97.91
NetR8_2: R8.2 U7.3 | length 2.2
  5V w0.254: R8.2@132.191,69.631 132.504,69.944 U7.3@134.298,69.944
NetR11_1: R11.1 U3.7 | length 2.1
  5V w0.254: R11.1@132.93,22.389 132.955,22.389 133.303,22.041 133.303,21.789 133.962,21.13 134.315,21.13 U3.7@134.322,21.123
NetR22_1: R22.1 R26.2 U5.3 | length 5.6
  5V w0.254: U5.3@133.473,6.56 131.699,4.786 R26.2@131.699,4.761 132.047,4.413 132.047,4.387 R22.1@133.821,2.613
NetR25_1: R25.1 U3.3 | length 2
  5V w0.254: R25.1@134.581,24.34 134.606,24.34 135.472,23.474 U3.3@135.472,22.773
NetR35_1: R35.1 R36.2 SW1.5 | length 5.5
  5V w0.254: R35.1@137.805,78.271 137.83,78.271 138.178,78.619 138.178,78.683 139.111,79.616 139.111,79.667 R36.2@139.459,80.015 141.098,80.015 SW1.5@142.1,79.014
NetR35_2: R35.2 SW1.6 | length 3.4
  5V w0.254: R35.2@139.405,78.271 140.343,78.271 SW1.6@142.1,76.514
NetR36_1: R36.1 R37.2 SW1.4 | length 5.1
  5V w0.254: R37.2@137.718,80.008 137.718,80.033 138.066,80.381 138.191,80.381 139.052,81.242 139.111,81.242 139.459,81.59 R36.1@139.459,81.615 139.56,81.514 SW1.4@142.1,81.514
NetR37_1: R37.1 R38.2 SW1.3 | length 5.4
  5V w0.254: R37.1@137.718,81.608 138.066,81.956 138.066,81.983 139.456,83.372 R38.2@139.456,83.397 141.223,83.397 141.84,84.014 SW1.3@142.1,84.014
NetR38_1: R38.1 R39.2 SW1.2 | length 5.7
  5V w0.254: R39.2@137.741,83.397 137.741,83.422 138.089,83.77 138.177,83.77 139.031,84.624 139.108,84.624 139.456,84.972 R38.1@139.456,84.997 140.583,84.997 SW1.2@142.1,86.514
NetR39_1: R39.1 R40.2 SW1.1 | length 6.4
  5V w0.254: R39.1@137.741,84.997 137.741,85.022 139.017,86.298 139.017,86.368 139.365,86.716 R40.2@139.39,86.716 140.34,86.716 141.731,88.106 141.731,88.644 SW1.1@142.1,89.014
pads on no net: J1.2 J4.1 J4.2 J4.3 J5.3 J5.4 J5.5 J5.6 J5.7 J5.8 J5.A2 J5.A3 J5.A6 J5.A7 J5.A8 J5.A10 J5.A11 J5.B2 J5.B3 J5.B6 J5.B7 J5.B8 J5.B10 J5.B11 J6.1 J6.2 J6.3 J7.1 J7.2 J7.3 J8.1 J8.2 J8.3 J9.1 J9.2 J9.3 J10.1 J10.2 J10.3 U3.4 U3.5 U3.6
copper on no net: | length 17316.8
